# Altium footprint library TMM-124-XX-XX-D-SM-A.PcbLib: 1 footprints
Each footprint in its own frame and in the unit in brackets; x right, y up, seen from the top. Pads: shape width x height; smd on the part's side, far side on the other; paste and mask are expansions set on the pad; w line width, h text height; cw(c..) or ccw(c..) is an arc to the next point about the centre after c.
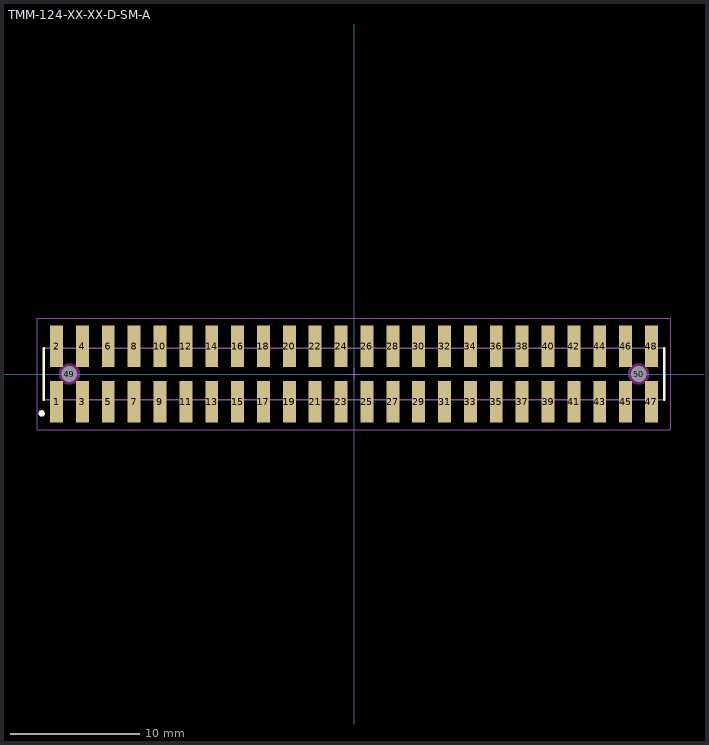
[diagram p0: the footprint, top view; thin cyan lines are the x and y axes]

## TMM-124-XX-XX-D-SM-A [mm] "2.00mm pitch, 48 pin, terminal strip; double row, w/alignment pins, SMT"
height 2.77
pads (50):
  rect 1x3.2 smd mask+0: 1(-23,-2.15) 2(-23,2.15) 3(-21,-2.15) 4(-21,2.15) 5(-19,-2.15) 6(-19,2.15) 7(-17,-2.15) 8(-17,2.15) 9(-15,-2.15) 10(-15,2.15) 11(-13,-2.15) 12(-13,2.15) 13(-11,-2.15) 14(-11,2.15) 15(-9,-2.15) 16(-9,2.15) 17(-7,-2.15) 18(-7,2.15) 19(-5,-2.15) 20(-5,2.15) 21(-3,-2.15) 22(-3,2.15) 23(-1,-2.15) 24(-1,2.15) 25(1,-2.15) 26(1,2.15) 27(3,-2.15) 28(3,2.15) 29(5,-2.15) 30(5,2.15) 31(7,-2.15) 32(7,2.15) 33(9,-2.15) 34(9,2.15) 35(11,-2.15) 36(11,2.15) 37(13,-2.15) 38(13,2.15) 39(15,-2.15) 40(15,2.15) 41(17,-2.15) 42(17,2.15) 43(19,-2.15) 44(19,2.15) 45(21,-2.15) 46(21,2.15) 47(23,-2.15) 48(23,2.15)
  round 1 hole 1.2 unplated mask+0: 49(-22,0) 50(22,0)
Top Overlay:
  circle w0.25: c-24.15,-3.05 r0.125
  lines w0.2: -24,-2 -24,2 ; 24,-2 24,2
Keep-Out Layer:
  pour cut-out: 22.807,0 22.779,0.209 22.699,0.403 22.571,0.571 22.403,0.699 22.209,0.779 22,0.807 21.791,0.779 21.597,0.699 21.429,0.571 21.301,0.403 21.221,0.209 21.193,0 21.221,-0.209 21.301,-0.403 21.429,-0.571 21.597,-0.699 21.791,-0.779 22,-0.807 22.209,-0.779 22.403,-0.699 22.571,-0.571 22.699,-0.403 22.779,-0.209
  pour cut-out: -21.193,0 -21.221,0.209 -21.301,0.403 -21.429,0.571 -21.597,0.699 -21.791,0.779 -22,0.807 -22.209,0.779 -22.403,0.699 -22.571,0.571 -22.699,0.403 -22.779,0.209 -22.807,0 -22.779,-0.209 -22.699,-0.403 -22.571,-0.571 -22.403,-0.699 -22.209,-0.779 -22,-0.807 -21.791,-0.779 -21.597,-0.699 -21.429,-0.571 -21.301,-0.403 -21.221,-0.209
Mechanical 12:
  lines w0.001: -24,-2 -24,2 24,2 24,-2 -24,-2
Mechanical 13:
  lines w0.1: -24,-2 -24,2 24,2 24,-2 -24,-2
  text ".Designator" at 0,-0.127 h1.52
Mechanical 15:
  lines w0.05: -0.5,0 0.5,0 ; 0,-0.5 0,0.5 ; -24.5,-4.3 -24.5,4.3 24.5,4.3 24.5,-4.3 -24.5,-4.3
